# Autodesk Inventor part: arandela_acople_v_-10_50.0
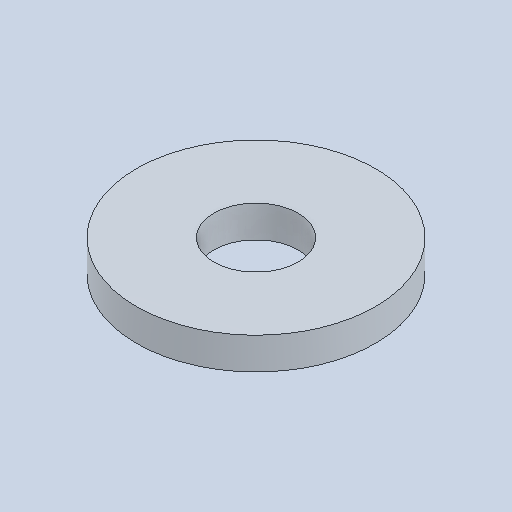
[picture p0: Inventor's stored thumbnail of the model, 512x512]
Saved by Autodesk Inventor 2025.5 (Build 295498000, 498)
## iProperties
Created: 2026-10
Part Number: arandela_acople_v_-10_50.0
Material: Genérico
Document SubType Name: Modeling
Designer: Luis M
Density: 1 g/cm^3
Appearance: Valor por defecto
Author: Luis M
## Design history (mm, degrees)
feature "Base1"
node "Sólido1"
